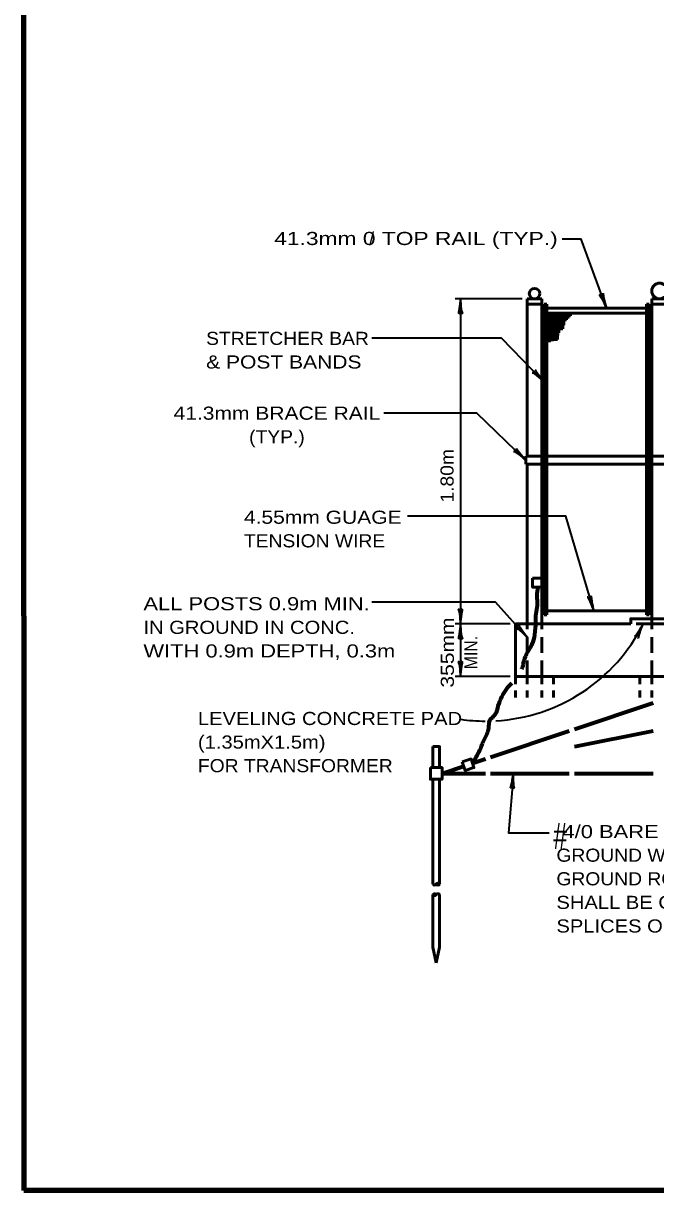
# Model space of a CAD drawing. Extents: x -30 to 826, y -11 to 533.
# Drawn here: x 27.5 to 172.3, y 0.9 to 268.1 of the extents above; entities that cross this region are included whole.
import ezdxf
from ezdxf.enums import TextEntityAlignment as Align

# ---------------------------------------------------------------- set-up
doc = ezdxf.new("R2010")
doc.units = 0
doc.header["$LTSCALE"] = 1.2
for name, pattern in [('LONG_DASHED', [7.5, 6, -1.5]), ('MEDIUM_DASHED', [4.5, 3, -1.5]), ('SHORT_DASHED', [2.7, 1.5, -1.2])]:
    doc.linetypes.add(name, pattern=pattern)
doc.layers.add('1', color=7, linetype='Continuous', lineweight=53)

msp = doc.modelspace()

# ---------------------------------------------------------------- linework, layer by layer
at = {"layer": '1', "lineweight": 35}
for p, q in [((141.719, 205.029), (126.419, 205.029)), ((139.019, 130.629), (126.419, 130.629)), ((139.019, 118.629), (126.419, 118.629))]:
    msp.add_line(p, q, dxfattribs=at)
at = {"layer": '1'}
for p, q in [((142.919, 205.029), (146.219, 205.029)), ((142.919, 169.029), (142.919, 205.029)), ((142.919, 203.829), (146.219, 203.829)), ((146.219, 169.029), (146.219, 205.029)), ((146.819, 169.029), (146.819, 203.829)), ((146.819, 203.829), (147.419, 203.829)), ((147.419, 169.029), (147.419, 203.829)), ((170.219, 203.829), (170.819, 203.829)), ((170.219, 169.029), (170.219, 203.829)), ((170.819, 169.029), (170.819, 203.829)), ((171.419, 205.029), (175.019, 205.029)), ((171.419, 169.029), (171.419, 205.029)), ((171.419, 203.829), (175.019, 203.829)), ((147.419, 202.929), (170.219, 202.929)), ((147.419, 201.729), (170.219, 201.729)), ((147.419, 201.129), (152.819, 201.129)), ((147.419, 200.529), (152.219, 200.529)), ((148.019, 195.129), (148.019, 201.729)), ((148.619, 195.309), (148.619, 201.729)), ((149.219, 195.429), (149.219, 201.729)), ((149.819, 195.729), (149.819, 201.729)), ((150.419, 198.129), (150.419, 201.729)), ((151.019, 198.129), (151.019, 201.729)), ((151.619, 199.929), (151.619, 201.729)), ((152.219, 200.529), (152.219, 201.729)), ((152.819, 201.129), (152.819, 201.729)), ((147.419, 199.929), (151.619, 199.929)), ((147.419, 199.329), (151.619, 199.329)), ((147.419, 198.729), (151.319, 198.729)), ((147.419, 198.129), (151.019, 198.129)), ((147.419, 197.529), (150.419, 197.529)), ((147.419, 196.929), (150.239, 196.929)), ((147.419, 196.329), (150.119, 196.329)), ((147.419, 195.729), (149.819, 195.729)), ((142.619, 169.029), (142.619, 167.229)), ((142.619, 169.029), (245.936, 169.029)), ((146.219, 167.529), (146.219, 168.729)), ((146.819, 167.529), (146.819, 168.729)), ((147.419, 167.529), (147.419, 168.729)), ((170.219, 168.729), (170.219, 167.529)), ((170.819, 168.729), (170.819, 167.529)), ((171.419, 168.729), (171.419, 167.529)), ((142.619, 167.229), (245.936, 167.229)), ((142.919, 130.629), (142.919, 167.229)), ((146.219, 130.629), (146.219, 167.229)), ((146.819, 132.729), (146.819, 167.229)), ((147.419, 132.729), (147.419, 167.229)), ((170.219, 132.729), (170.219, 167.229)), ((170.819, 132.729), (170.819, 167.229)), ((171.419, 131.829), (171.419, 167.229)), ((147.419, 133.629), (170.219, 133.629)), ((146.819, 132.729), (147.419, 132.729)), ((170.219, 132.729), (170.819, 132.729)), ((140.219, 118.629), (140.219, 130.629)), ((140.219, 130.629), (166.619, 130.629)), ((140.219, 118.629), (192.119, 118.629)), ((121.319, 97.779), (121.319, 102.579)), ((121.319, 95.079), (121.319, 71.079)), ((122.819, 95.079), (122.819, 71.079)), ((121.319, 68.679), (121.319, 56.679)), ((122.819, 68.679), (122.819, 56.679)), ((121.319, 56.679), (122.069, 53.079)), ((122.819, 56.679), (122.069, 53.079))]:
    msp.add_line(p, q, dxfattribs=at)
at = {"layer": '1', "linetype": 'MEDIUM_DASHED'}
for p, q in [((171.419, 118.629), (171.419, 131.829)), ((142.919, 118.629), (142.919, 130.629)), ((146.219, 118.629), (146.219, 130.629))]:
    msp.add_line(p, q, dxfattribs=at)
at = {"layer": '1', "linetype": 'LONG_DASHED'}
msp.add_line((167.819, 130.629), (226.619, 130.629), dxfattribs=at)
at = {"layer": '1', "linetype": 'SHORT_DASHED'}
for p, q in [((140.219, 118.629), (140.219, 113.829)), ((142.919, 118.629), (142.919, 113.829)), ((146.219, 118.629), (146.219, 113.829)), ((148.919, 118.629), (148.919, 113.829)), ((168.719, 118.629), (168.719, 113.829)), ((171.419, 118.629), (171.419, 113.829))]:
    msp.add_line(p, q, dxfattribs=at)
at = {"layer": '1', "lineweight": 70}
for p, q in [((153.719, 106.555), (171.719, 112.57)), ((134.519, 100.139), (152.519, 106.154)), ((171.719, 106.072), (153.719, 102.479)), ((130.361, 98.749), (133.319, 99.738)), ((123.419, 96.429), (128.369, 98.083)), ((123.419, 96.429), (133.319, 96.429)), ((134.519, 96.429), (152.519, 96.429)), ((153.719, 96.429), (171.719, 96.429))]:
    msp.add_line(p, q, dxfattribs=at)
at = {"layer": '1', "lineweight": 158}
msp.add_line((819.196, 0.944), (27.596, 0.944), dxfattribs=at)
msp.add_lwpolyline([(819.196, 527.044), (27.496, 526.944), (27.596, 0.944)], dxfattribs=at)
at = {"layer": '1', "lineweight": 35}
for points in [[(161.031, 202.929), (155.293, 218.713), (150.933, 218.713)], [(127.619, 205.029), (127.619, 130.629), (127.619, 118.629)], [(146.819, 185.991), (136.985, 196.06), (107.305, 196.06)], [(142.619, 168.061), (131.346, 178.904), (110.089, 178.904)], [(158.135, 133.629), (151.718, 155.282), (115.454, 155.282)], [(142.919, 127.558), (135.615, 135.606), (107.305, 135.606)], [(139.73, 96.429), (138.62, 82.865), (147.914, 82.865)]]:
    msp.add_lwpolyline(points, dxfattribs=at)
at = {"layer": '1'}
for points in [[(144.12, 141.13), (146.22, 141.129), (146.219, 139.029), (144.119, 139.03)], [(128.036, 99.079), (130.028, 99.745), (130.694, 97.753), (128.702, 97.088)], [(120.719, 97.779), (123.419, 97.779), (123.419, 95.079), (120.719, 95.079)]]:
    msp.add_lwpolyline(points, close=True, dxfattribs=at)
for points in [[(320.819, 130.629), (294.419, 130.629), (294.419, 131.829), (232.019, 131.829), (232.019, 130.629), (227.819, 130.629), (227.819, 131.829), (166.619, 131.829), (166.619, 130.629)], [(122.819, 97.779), (122.819, 102.579), (121.319, 102.579)]]:
    msp.add_lwpolyline(points, dxfattribs=at)
for centre, radius in [((173.219, 206.829), 1.8), ((144.569, 206.229), 1.2)]:
    msp.add_circle(centre, radius, dxfattribs=at)
at = {"layer": '1', "lineweight": 35}
for start, end in [(273.19613, 333.34814), (261.86999, 269.7196)]:
    msp.add_arc((133.435, 148.713), 40.315, start, end, dxfattribs=at)
at = {"layer": '1'}
for centre, start, end in [((121.694, 71.295), 209.9406, 330.0594), ((122.444, 70.863), 29.9406, 150.0594), ((122.444, 71.295), 209.9406, 330.0594), ((121.694, 68.463), 29.9406, 150.0594), ((121.694, 68.895), 209.9406, 330.0594), ((122.444, 68.463), 29.9406, 150.0594)]:
    msp.add_arc(centre, 0.433, start, end, dxfattribs=at)
at = {"layer": '1', "lineweight": 40}
for centre, major_axis, ratio, start_param, end_param in [((160.272, 204.047), (0.908, -1.95), 0.122415, 0.8963533, 3.1415927), ((160.272, 204.047), (0.908, -1.95), 0.122415, 0.8963533, 3.1415927), ((160.81, 204.28), (-0.522, 2.053), 0.07063, 6.2823074, 8.5597026), ((160.81, 204.28), (-0.522, 2.053), 0.07063, 6.2823074, 8.5597026), ((127.365, 203.685), (0.211, 2.108), 0.07063, 3.1407148, 5.41811), ((127.365, 203.685), (0.211, 2.108), 0.07063, 3.1407148, 5.41811), ((127.951, 203.72), (-0.187, 2.143), 0.122415, 0.8963533, 3.1415927), ((127.951, 203.72), (-0.187, 2.143), 0.122415, 0.8963533, 3.1415927), ((145.667, 186.696), (1.631, -1.402), 0.122415, 0.8963533, 3.1415927), ((145.667, 186.696), (1.631, -1.402), 0.122415, 0.8963533, 3.1415927), ((146.061, 187.131), (-1.322, 1.655), 0.07063, 6.2823074, 8.5597026), ((146.061, 187.131), (-1.322, 1.655), 0.07063, 6.2823074, 8.5597026), ((141.446, 168.729), (1.674, -1.35), 0.122415, 0.8963533, 3.1415927), ((141.826, 169.176), (-1.373, 1.613), 0.07063, 6.2823074, 8.5597026), ((157.445, 134.79), (0.789, -2.001), 0.122415, 0.8963533, 3.1415927), ((157.445, 134.79), (0.789, -2.001), 0.122415, 0.8963533, 3.1415927), ((157.997, 134.991), (0.397, -2.081), 0.07063, 3.1407148, 5.41811), ((157.997, 134.991), (0.397, -2.081), 0.07063, 3.1407148, 5.41811), ((127.288, 131.939), (0.187, -2.143), 0.122415, 0.8963533, 3.1415927), ((127.288, 131.939), (0.187, -2.143), 0.122415, 0.8963533, 3.1415927), ((127.873, 131.974), (-0.211, -2.108), 0.07063, 3.1407148, 5.41811), ((127.873, 131.974), (-0.211, -2.108), 0.07063, 3.1407148, 5.41811), ((127.365, 129.285), (0.211, 2.108), 0.07063, 3.1407148, 5.41811), ((127.951, 129.32), (-0.187, 2.143), 0.122415, 0.8963533, 3.1415927), ((141.794, 128.305), (1.579, -1.461), 0.122415, 0.8963533, 3.1415927), ((142.203, 128.725), (-1.26, 1.702), 0.07063, 6.2823074, 8.5597026), ((168.637, 129.541), (1.134, 1.789), 0.07063, 3.1407148, 5.41811), ((168.637, 129.541), (1.134, 1.789), 0.07063, 3.1407148, 5.41811), ((169.176, 129.31), (0.794, 1.999), 0.122415, 0.8963533, 3.1415927), ((169.176, 129.31), (0.794, 1.999), 0.122415, 0.8963533, 3.1415927), ((127.288, 119.939), (0.187, -2.143), 0.122415, 0.8963533, 3.1415927), ((127.873, 119.974), (-0.211, -2.108), 0.07063, 3.1407148, 5.41811), ((139.367, 95.11), (-0.382, -2.084), 0.07063, 6.2823074, 8.5597026), ((139.953, 95.097), (-0.012, 2.151), 0.122415, 0.8963533, 3.1415927)]:
    msp.add_ellipse(centre, major_axis=major_axis, ratio=ratio, start_param=start_param, end_param=end_param, dxfattribs=at)
at = {"layer": '1', "lineweight": 70}
for points in [[(145.292, 139.052), (145.106, 137.124), (145.168, 134.885), (144.857, 132.957), (144.795, 131.153), (144.546, 128.106), (143.986, 125.991), (143.8, 125.618), (142.992, 124.25), (142.432, 123.068), (141.997, 121.762), (141.81, 120.829), (141.562, 120.269)], [(130.361, 98.749), (132.049, 101.736), (133.106, 104.286), (134.101, 106.773), (134.35, 108.515), (135.593, 109.945), (136.277, 111.873), (137.085, 113.926), (138.204, 115.791), (139.386, 117.098)]]:
    msp.add_spline(points, degree=3, dxfattribs=at)

# ---------------------------------------------------------------- texts
at = {"layer": '1'}
for s, width, p in [('41.3mm 0 TOP RAIL (TYP.)', 1.3, (117.421, 217.343)), ('41.3mm BRACE RAIL', 1.2, (85.577, 177.367)), ('(TYP.)', 1.1, (85.577, 171.967))]:
    msp.add_text(s, height=3, dxfattribs=dict(at, width=width)).set_placement(p, align=Align.CENTER)
msp.add_text('/', height=3, dxfattribs=at).set_placement((107.273, 217.343), align=Align.CENTER)
for s, height, width, p in [('STRETCHER BAR', 3, 1.1, (69.366, 194.481)), ('& POST BANDS', 3, 1.2, (69.366, 189.081)), ('4.55mm GUAGE', 3, 1.2, (78.012, 153.553)), ('TENSION WIRE', 3, 1.1, (78.012, 148.153)), ('ALL POSTS 0.9m MIN.', 3, 1.25, (55.003, 133.759)), ('IN GROUND IN CONC.', 3, 1.15, (55.003, 128.359)), ('WITH 0.9m DEPTH, 0.3m', 3, 1.25, (55.003, 122.959)), ('LEVELING CONCRETE PAD', 3, 1.15, (67.48, 107.5)), ('(1.35mX1.5m)', 3, 1.15, (67.48, 102.1)), ('FOR TRANSFORMER', 3, 1.1, (67.48, 96.7)), ('#', 6, 0.7, (148.885, 79.127)), (' 4/0 BARE TINNED COPPER', 3, 1.25, (149.589, 81.613)), ('GROUND WIRE. THERMO-WELD TO', 3, 1.1, (149.589, 76.213)), ('GROUND RODS. GROUND WIRES', 3, 1.1, (149.589, 70.813)), ('SHALL BE CONTINUOUS WITHOUT', 3, 1.15, (149.589, 65.413)), ('SPLICES OR BREAKS.', 3, 1.15, (149.589, 60.013))]:
    msp.add_text(s, height=height, dxfattribs=dict(at, width=width)).set_placement(p)
for s, width, p in [('1.80m', 1.1, (126.042, 164.529)), ('355mm', 1.2, (126.11, 124.09)), ('MIN.', 0.9, (131.51, 124.09))]:
    msp.add_text(s, height=3, rotation=90, dxfattribs=dict(at, width=width)).set_placement(p, align=Align.CENTER)

doc.saveas('drawing.dxf')
